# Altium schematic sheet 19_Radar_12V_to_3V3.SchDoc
size 289 x 401 mm
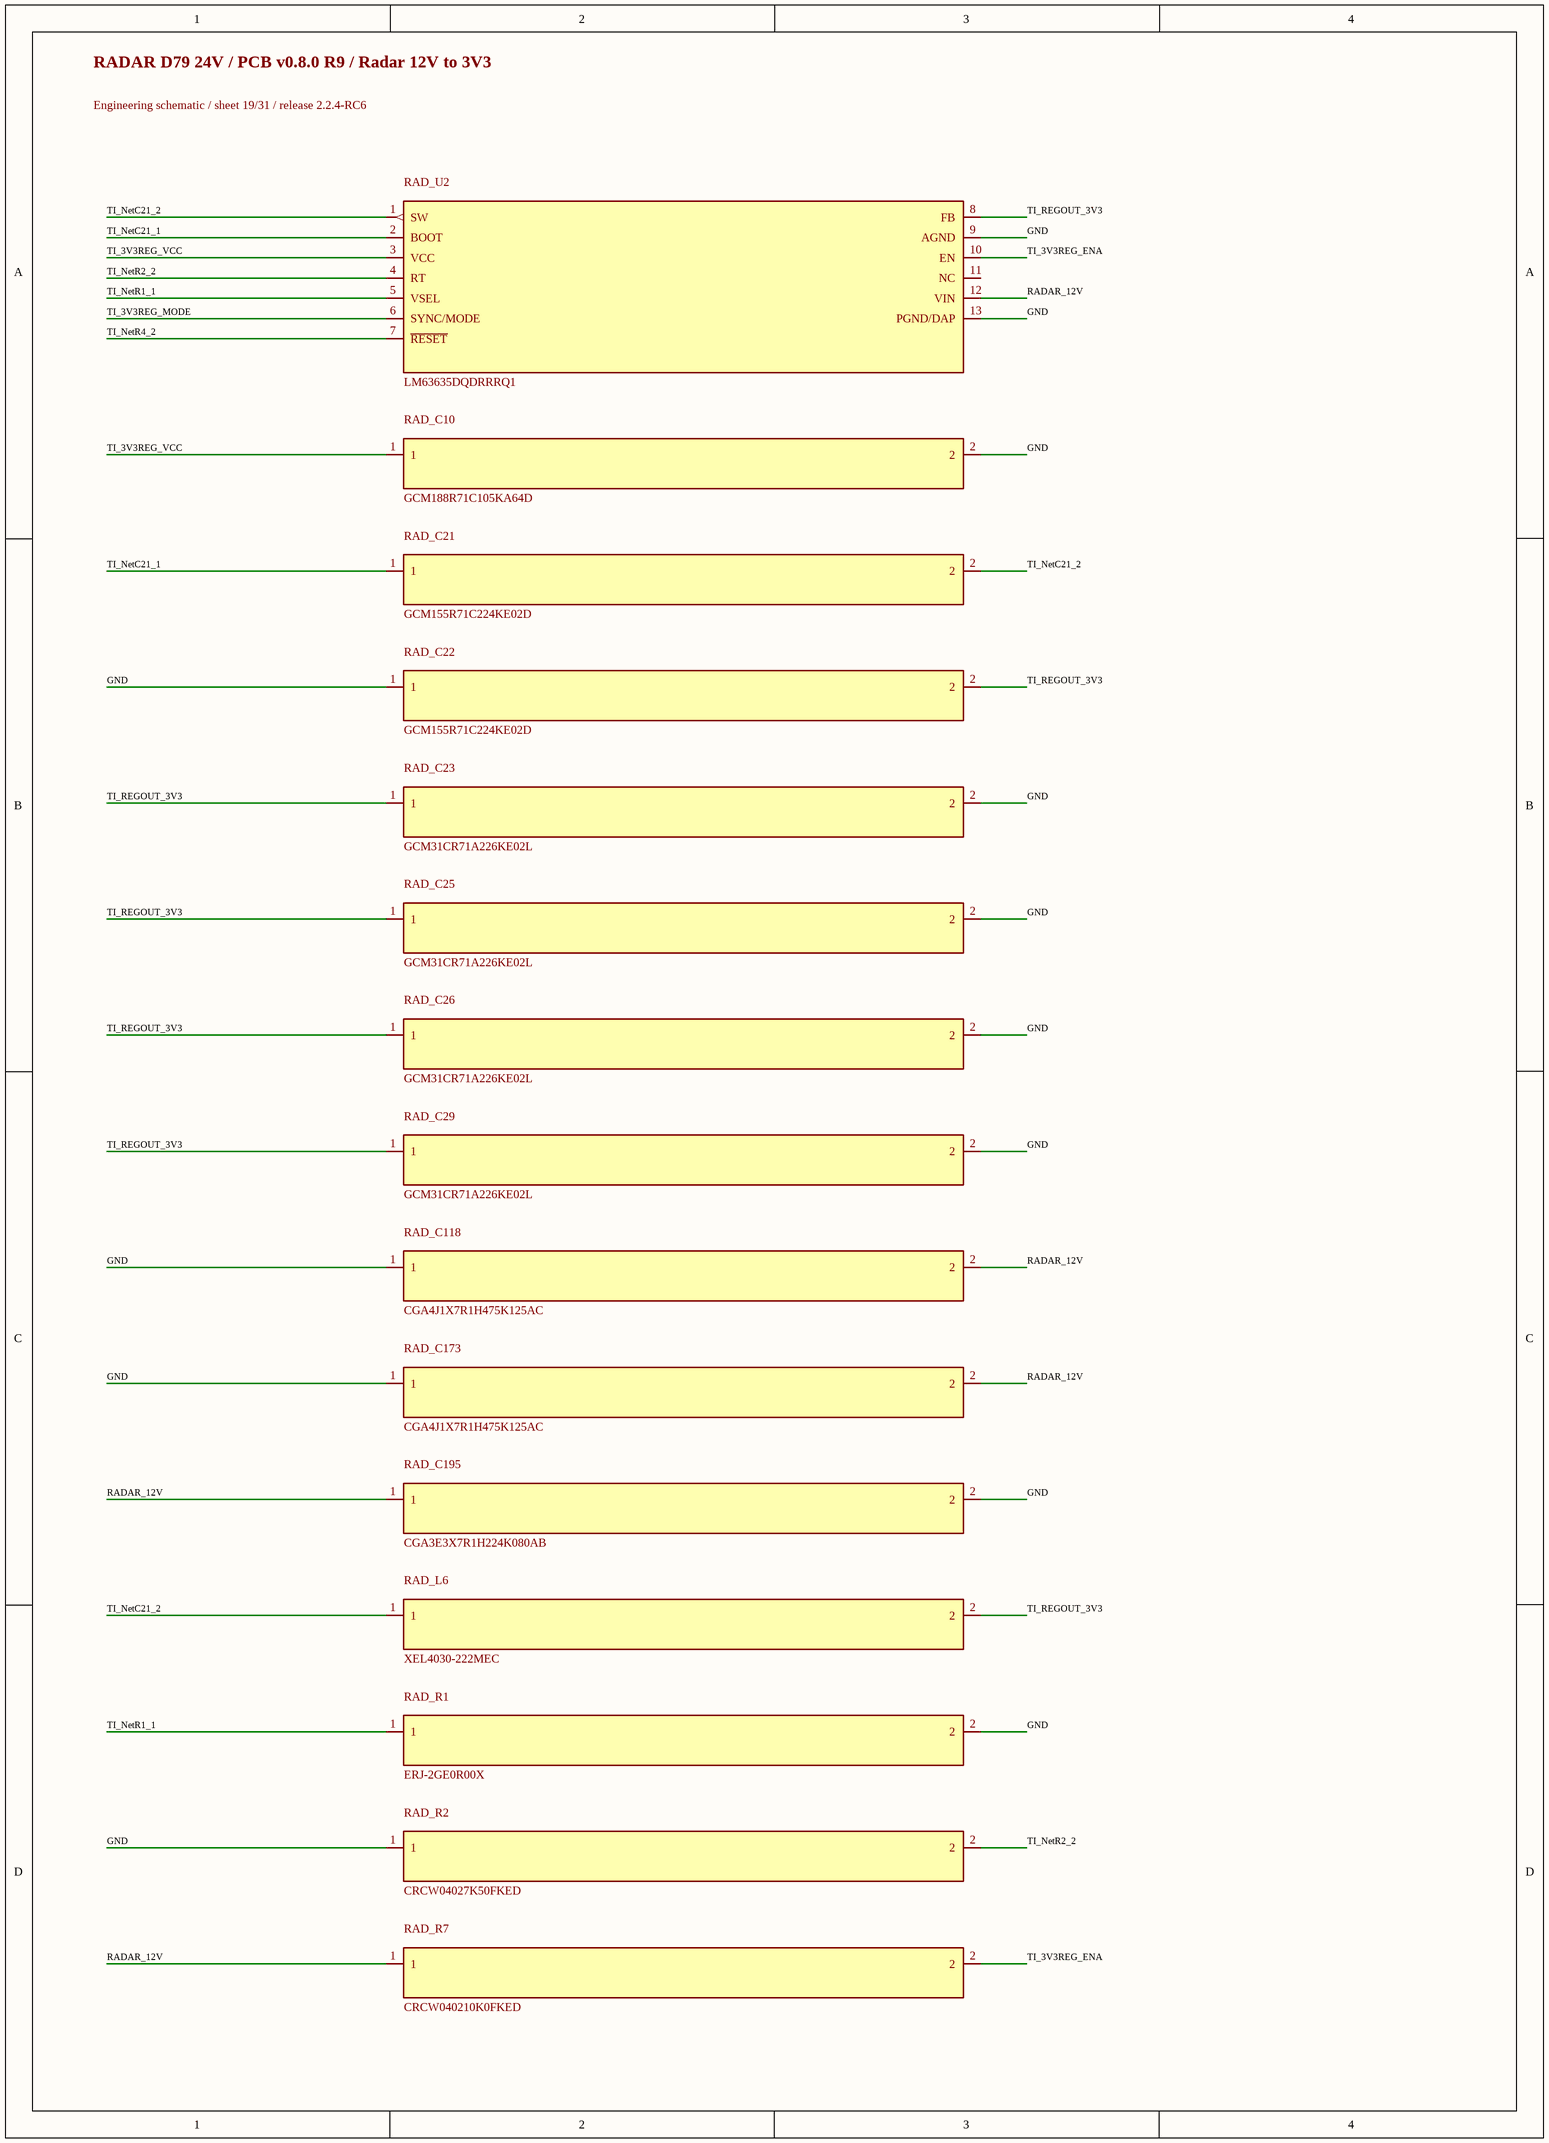
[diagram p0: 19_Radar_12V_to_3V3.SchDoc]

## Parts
RAD_C10  GCM188R71C105KA64D  [0603L]
RAD_C21  GCM155R71C224KE02D  [0402L]
RAD_C22  GCM155R71C224KE02D  [0402L]
RAD_C23  GCM31CR71A226KE02L  [1206_180L]
RAD_C25  GCM31CR71A226KE02L  [1206_180L]
RAD_C26  GCM31CR71A226KE02L  [1206_180L]
RAD_C29  GCM31CR71A226KE02L  [1206_180L]
RAD_C118  CGA4J1X7R1H475K125AC  [FP-CGA4J1X7R1H475K125AC_0805-MFG]
RAD_C173  CGA4J1X7R1H475K125AC  [FP-CGA4J1X7R1H475K125AC_0805-MFG]
RAD_C195  CGA3E3X7R1H224K080AB  [0603L]
RAD_L6  XEL4030-222MEC  [FP-XEL4030-222MEC_SMT2_4MM0_4MM0-MFG]
RAD_R1  ERJ-2GE0R00X  [0402L]
RAD_R2  CRCW04027K50FKED  [0402L]
RAD_R7  CRCW040210K0FKED  [0402L]
RAD_U2  LM63635DQDRRRQ1  [DRR0012E-MFG]

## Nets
GND: RAD_C10.2 RAD_C22.1 RAD_C23.2 RAD_C25.2 RAD_C26.2 RAD_C29.2 RAD_C118.1 RAD_C173.1 RAD_C195.2 RAD_R1.2 RAD_R2.1 RAD_U2.9(AGND) RAD_U2.13(PGND/DAP)
RADAR_12V: RAD_C118.2 RAD_C173.2 RAD_C195.1 RAD_R7.1 RAD_U2.12(VIN)
TI_3V3REG_ENA: RAD_R7.2 RAD_U2.10(EN)
TI_3V3REG_MODE: RAD_U2.6(SYNC/MODE)
TI_3V3REG_VCC: RAD_C10.1 RAD_U2.3(VCC)
TI_NetC21_1: RAD_C21.1 RAD_U2.2(BOOT)
TI_NetC21_2: RAD_C21.2 RAD_L6.1 RAD_U2.1(SW)
TI_NetR1_1: RAD_R1.1 RAD_U2.5(VSEL)
TI_NetR2_2: RAD_R2.2 RAD_U2.4(RT)
TI_NetR4_2: RAD_U2.7(~{RESET})
TI_REGOUT_3V3: RAD_C22.2 RAD_C23.1 RAD_C25.1 RAD_C26.1 RAD_C29.1 RAD_L6.2 RAD_U2.8(FB)

Not connected (* = marked no-connect by the designer): RAD_U2 11(NC)

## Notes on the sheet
- RADAR D79 24V / PCB v0.8.0 R9 / Radar 12V to 3V3
- Engineering schematic / sheet 19/31 / release 2.2.4-RC6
